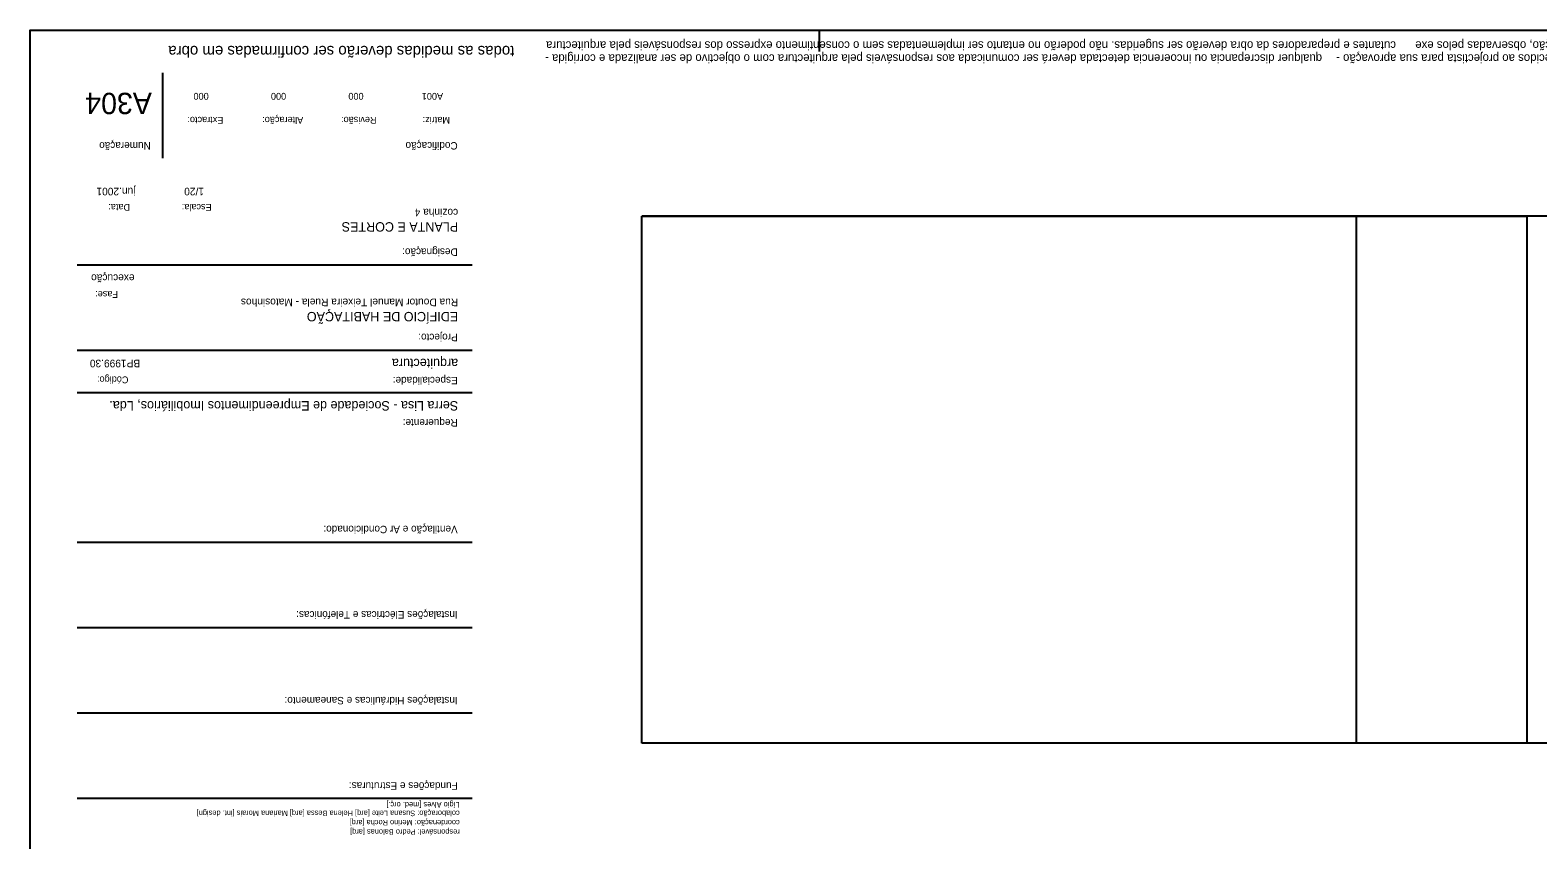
# Model space of a CAD drawing. Extents: x 1329.4 to 1341, y -313.7 to -303.3.
# Drawn here: x 1329.39 to 1336.46, y -307.11 to -303.32 of the extents above; entities that cross this region are included whole.
import ezdxf

# ---------------------------------------------------------------- set-up
doc = ezdxf.new("R2010")
doc.units = 0
for name, color, linetype in [('Level 1', 7, 'Continuous'), ('Level 13', 7, 'Continuous'), ('Level 2', 7, 'Continuous'), ('Level 62', 7, 'Continuous')]:
    doc.layers.add(name, color=color, linetype=linetype)

msp = doc.modelspace()

# ---------------------------------------------------------------- linework, layer by layer
at = {"layer": 'Level 1'}
for p, q in [((1338.6068, -304.1895), (1332.2571, -304.1895)), ((1332.2571, -306.6595), (1332.2571, -304.1895)), ((1338.6068, -306.6595), (1332.2571, -306.6595))]:
    msp.add_line(p, q, dxfattribs=at)
at = {"layer": 'Level 13'}
for p, q in [((1336.4074, -304.1905), (1332.2571, -304.1905)), ((1335.6074, -306.6595), (1335.6074, -304.1905))]:
    msp.add_line(p, q, dxfattribs=at)
at = {"layer": 'Level 2'}
msp.add_line((1336.4074, -306.6595), (1336.4074, -304.1895), dxfattribs=at)
at = {"layer": 'Level 62'}
for p, q in [((1333.09, -303.4179), (1333.09, -303.3179)), ((1330.01, -303.5181), (1330.01, -303.9181)), ((1329.61, -304.4181), (1331.462, -304.4181)), ((1329.61, -304.8181), (1331.462, -304.8181)), ((1331.462, -305.0181), (1329.61, -305.0181)), ((1331.462, -305.7181), (1329.61, -305.7181)), ((1331.462, -306.1181), (1329.61, -306.1181)), ((1331.462, -306.5181), (1329.61, -306.5181)), ((1331.462, -306.9181), (1329.61, -306.9181))]:
    msp.add_line(p, q, dxfattribs=at)
msp.add_lwpolyline([(1340.9896, -303.3179), (1340.9896, -313.7129), (1329.39, -313.7129), (1329.39, -303.3179)], close=True, dxfattribs=at)

# ---------------------------------------------------------------- texts
for s, height, rotation, p in [('todas as medidas deverão ser confirmadas em obra', 0.0526, 180, (1331.6597, -303.3916)), ('cutantes e preparadores da obra deverão ser sugeridas. não poderão no entanto ser implementadas sem o consentimento expresso dos responsáveis pela arquitectura', 0.0399996, 180, (1335.7925, -303.37)), ('a introdução de alterações com o objectivo de melhorar os métodos construtivos, a redução de custos, desperdícios e tempo de execução, observadas pelos exe', 0.0399996, 180, (1339.7123, -303.37)), ('qualquer discrepancia ou incoerencia detectada deverá ser comunicada aos responsáveis pela arquitectura com o objectivo de ser analizada e corrigida -', 0.0399996, 180, (1335.4459, -303.431)), ('os desenhos de preparação de obra deverão ser fornecidos ao projectista para sua aprovação -', 0.04, 180, (1337.7833, -303.431)), ('A304', 0.09999, 179.99997, (1329.9605, -303.6113)), ('000', 0.03199, 179.99997, (1330.227, -303.6117)), ('000', 0.032, 179.99997, (1330.59, -303.6117)), ('000', 0.03199, 179.99997, (1330.953, -303.6117)), ('A001', 0.032, 179.99997, (1331.3256, -303.6119)), ('Extracto:', 0.03199, 179.99997, (1330.2958, -303.7241)), ('Alteração:', 0.03199, 179.99997, (1330.6702, -303.7241)), ('Revisão:', 0.03199, 179.99997, (1331.0136, -303.7241)), ('Matriz:', 0.03199, 179.99997, (1331.3578, -303.7243)), ('Numeração', 0.03499, 179.99997, (1329.9554, -303.8425)), ('Codificação', 0.034993, 179.99997, (1331.394, -303.8423)), ('jun.2001', 0.0356, 179.99997, (1329.8836, -304.0563)), ('1/20', 0.0356, 179.99997, (1330.2047, -304.0563)), ('Data:', 0.03199, 179.99997, (1329.8584, -304.1325)), ('Escala:', 0.03199, 179.99997, (1330.2408, -304.1325)), ('cozinha 4', 0.03559, 179.99997, (1331.3962, -304.1551)), ('PLANTA E CORTES', 0.04399, 179.99997, (1331.3962, -304.2177)), ('Designação:', 0.034993, 179.99997, (1331.394, -304.3405)), ('execução', 0.0356, 179.99997, (1329.8794, -304.4621)), ('Fase:', 0.03199, 179.99997, (1329.8016, -304.5405)), ('Rua Doutor Manuel Teixeira Ruela - Matosinhos', 0.035589, 179.99997, (1331.3962, -304.5757)), ('EDIFÍCIO DE HABITAÇÃO', 0.043989, 179.99997, (1331.3962, -304.6383)), ('Projecto:', 0.03499, 179.99997, (1331.394, -304.7405)), ('BP1999.30', 0.0356, 179.99997, (1329.9056, -304.8621)), ('arquitectura', 0.043993, 179.99997, (1331.3962, -304.8577)), ('Código:', 0.03199, 179.99997, (1329.8508, -304.9405)), ('Especialidade:', 0.034993, 179.99997, (1331.394, -304.9425)), ('Serra Lisa - Sociedade de Empreendimentos Imobiliários, Lda.', 0.043999, 179.99997, (1331.3964, -305.0563)), ('Requerente:', 0.034993, 179.99997, (1331.394, -305.1405)), ('Ventilação e Ar Condicionado:', 0.034997, 179.99997, (1331.394, -305.6403)), ('Instalações Eléctricas e Telefónicas:', 0.034997, 179.99997, (1331.394, -306.0403)), ('Instalações Hidráulicas e Saneamento:', 0.034997, 179.99997, (1331.394, -306.4423)), ('Fundações e Estruturas:', 0.034997, 179.99997, (1331.394, -306.8423)), ('Lígio Alves [med. orç.]', 0.026, 179.99995, (1331.4036, -306.935)), ('colaboração: Susana Leite [arq] Helena Bessa [arq] Mariana Morais [int. design]', 0.026, 179.99995, (1331.4036, -306.975)), ('coordenação: Merino Rocha [arq]', 0.026, 179.99995, (1331.4036, -307.0188)), ('responsável: Pedro Balonas [arq]', 0.026, 179.99995, (1331.4036, -307.0626))]:
    msp.add_text(s, height=height, rotation=rotation, dxfattribs=at).set_placement(p)

doc.saveas('drawing.dxf')
